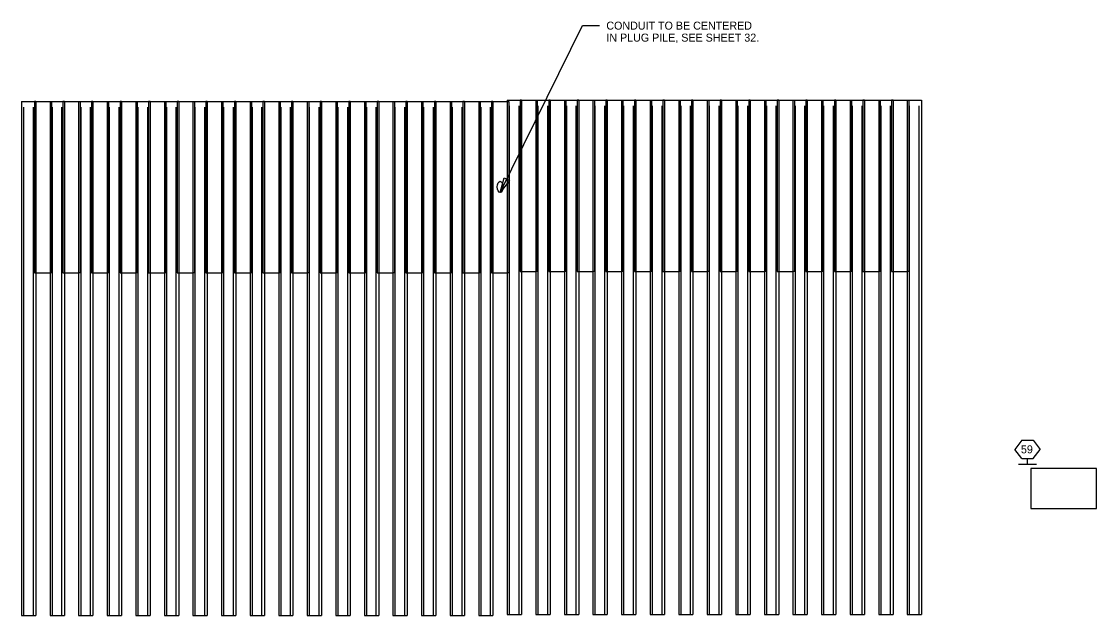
# Model space of a CAD drawing. Extents: x -190 to 421, y 1 to 366.
# Drawn here: x -189.8 to -1.7, y 261.9 to 365.9 of the extents above; entities that cross this region are included whole.
import ezdxf

# ---------------------------------------------------------------- set-up
doc = ezdxf.new("R2010")
doc.units = 0
for name, color, linetype in [('BR_P_Beam_Reinforcing', 7, 'Continuous'), ('DR_P_Culvert', 7, 'Continuous'), ('RD_P_Wall', 7, 'Continuous'), ('SH_Data', 7, 'Continuous')]:
    doc.layers.add(name, color=color, linetype=linetype)

msp = doc.modelspace()

# ---------------------------------------------------------------- linework, layer by layer
at = {"layer": 'BR_P_Beam_Reinforcing'}
for p, q in [((-189.38, 261.93), (-189.38, 350.93)), ((-187.71, 261.93), (-187.71, 350.93)), ((-184.38, 261.93), (-184.38, 350.93)), ((-182.71, 261.93), (-182.71, 350.93)), ((-179.38, 261.93), (-179.38, 350.93)), ((-177.71, 261.93), (-177.71, 350.93)), ((-174.38, 261.93), (-174.38, 350.93)), ((-172.71, 261.93), (-172.71, 350.93)), ((-169.38, 261.93), (-169.38, 350.93)), ((-167.71, 261.93), (-167.71, 350.93)), ((-164.38, 261.93), (-164.38, 350.93)), ((-162.71, 261.93), (-162.71, 350.93)), ((-159.38, 261.93), (-159.38, 350.93)), ((-157.71, 261.93), (-157.71, 350.93)), ((-154.38, 261.93), (-154.38, 350.93)), ((-152.71, 261.93), (-152.71, 350.93)), ((-149.38, 261.93), (-149.38, 350.93)), ((-147.71, 261.93), (-147.71, 350.93)), ((-144.38, 261.93), (-144.38, 350.93)), ((-142.71, 261.93), (-142.71, 350.93)), ((-139.38, 261.93), (-139.38, 350.93)), ((-137.71, 261.93), (-137.71, 350.93)), ((-134.38, 261.93), (-134.38, 350.93)), ((-132.71, 261.93), (-132.71, 350.93)), ((-129.38, 261.93), (-129.38, 350.93)), ((-127.71, 261.93), (-127.71, 350.93)), ((-124.38, 261.93), (-124.38, 350.93)), ((-122.71, 261.93), (-122.71, 350.93)), ((-119.38, 261.93), (-119.38, 350.93)), ((-117.71, 261.93), (-117.71, 350.93)), ((-114.38, 261.93), (-114.38, 350.93)), ((-112.71, 261.93), (-112.71, 350.93)), ((-109.38, 261.93), (-109.38, 350.93)), ((-107.71, 261.93), (-107.71, 350.93)), ((-104.38, 262.13), (-104.38, 351.13)), ((-102.71, 262.13), (-102.71, 351.13)), ((-99.38, 262.13), (-99.38, 351.13)), ((-97.71, 262.13), (-97.71, 351.13)), ((-94.38, 262.13), (-94.38, 351.13)), ((-92.71, 262.13), (-92.71, 351.13)), ((-89.38, 262.13), (-89.38, 351.13)), ((-87.71, 262.13), (-87.71, 351.13)), ((-84.38, 262.13), (-84.38, 351.13)), ((-82.71, 262.13), (-82.71, 351.13)), ((-79.38, 262.13), (-79.38, 351.13)), ((-77.71, 262.13), (-77.71, 351.13)), ((-74.38, 262.13), (-74.38, 351.13)), ((-72.71, 262.13), (-72.71, 351.13)), ((-69.38, 262.13), (-69.38, 351.13)), ((-67.71, 262.13), (-67.71, 351.13)), ((-64.38, 262.13), (-64.38, 351.13)), ((-62.71, 262.13), (-62.71, 351.13)), ((-59.38, 262.13), (-59.38, 351.13)), ((-57.71, 262.13), (-57.71, 351.13)), ((-54.38, 262.13), (-54.38, 351.13)), ((-52.71, 262.13), (-52.71, 351.13)), ((-49.38, 262.13), (-49.38, 351.13)), ((-47.71, 262.13), (-47.71, 351.13)), ((-44.38, 262.13), (-44.38, 351.13)), ((-42.71, 262.13), (-42.71, 351.13)), ((-39.38, 262.13), (-39.38, 351.13)), ((-37.71, 262.13), (-37.71, 351.13)), ((-34.38, 262.13), (-34.38, 351.13)), ((-32.71, 262.13), (-32.71, 351.13))]:
    msp.add_line(p, q, dxfattribs=at)
at = {"layer": 'DR_P_Culvert'}
msp.add_ellipse((-106.04, 336.95), major_axis=(0, 1), ratio=0.5, dxfattribs=at)
at = {"layer": 'RD_P_Wall'}
for p, q in [((-189.79, 351.93), (-187.29, 351.93)), ((-189.79, 351.93), (-189.79, 261.93)), ((-187.29, 351.93), (-184.79, 351.93)), ((-187.29, 351.93), (-187.29, 261.93)), ((-184.79, 351.93), (-182.29, 351.93)), ((-184.79, 351.93), (-184.79, 261.93)), ((-182.29, 351.93), (-182.29, 261.93)), ((-182.29, 351.93), (-179.79, 351.93)), ((-179.79, 351.93), (-177.29, 351.93)), ((-179.79, 351.93), (-179.79, 261.93)), ((-177.29, 351.93), (-177.29, 261.93)), ((-177.29, 351.93), (-174.79, 351.93)), ((-174.79, 351.93), (-172.29, 351.93)), ((-174.79, 351.93), (-174.79, 261.93)), ((-172.29, 351.93), (-172.29, 261.93)), ((-172.29, 351.93), (-169.79, 351.93)), ((-169.79, 351.93), (-167.29, 351.93)), ((-169.79, 351.93), (-169.79, 261.93)), ((-167.29, 351.93), (-167.29, 261.93)), ((-167.29, 351.93), (-164.79, 351.93)), ((-164.79, 351.93), (-162.29, 351.93)), ((-164.79, 351.93), (-164.79, 261.93)), ((-162.29, 351.93), (-162.29, 261.93)), ((-162.29, 351.93), (-159.79, 351.93)), ((-159.79, 351.93), (-157.29, 351.93)), ((-159.79, 351.93), (-159.79, 261.93)), ((-157.29, 351.93), (-157.29, 261.93)), ((-157.29, 351.93), (-154.79, 351.93)), ((-154.79, 351.93), (-152.29, 351.93)), ((-154.79, 351.93), (-154.79, 261.93)), ((-152.29, 351.93), (-152.29, 261.93)), ((-152.29, 351.93), (-149.79, 351.93)), ((-149.79, 351.93), (-147.29, 351.93)), ((-149.79, 351.93), (-149.79, 261.93)), ((-147.29, 351.93), (-147.29, 261.93)), ((-147.29, 351.93), (-144.79, 351.93)), ((-144.79, 351.93), (-142.29, 351.93)), ((-144.79, 351.93), (-144.79, 261.93)), ((-142.29, 351.93), (-142.29, 261.93)), ((-142.29, 351.93), (-139.79, 351.93)), ((-139.79, 351.93), (-137.29, 351.93)), ((-139.79, 351.93), (-139.79, 261.93)), ((-137.29, 351.93), (-137.29, 261.93)), ((-137.29, 351.93), (-134.79, 351.93)), ((-134.79, 351.93), (-132.29, 351.93)), ((-134.79, 351.93), (-134.79, 261.93)), ((-132.29, 351.93), (-132.29, 261.93)), ((-132.29, 351.93), (-129.79, 351.93)), ((-129.79, 351.93), (-127.29, 351.93)), ((-129.79, 351.93), (-129.79, 261.93)), ((-127.29, 351.93), (-127.29, 261.93)), ((-127.29, 351.93), (-124.79, 351.93)), ((-124.79, 351.93), (-122.29, 351.93)), ((-124.79, 351.93), (-124.79, 261.93)), ((-122.29, 351.93), (-122.29, 261.93)), ((-122.29, 351.93), (-119.79, 351.93)), ((-119.79, 351.93), (-117.29, 351.93)), ((-119.79, 351.93), (-119.79, 261.93)), ((-117.29, 351.93), (-117.29, 261.93)), ((-117.29, 351.93), (-114.79, 351.93)), ((-114.79, 351.93), (-112.29, 351.93)), ((-114.79, 351.93), (-114.79, 261.93)), ((-112.29, 351.93), (-112.29, 261.93)), ((-112.29, 351.93), (-109.79, 351.93)), ((-109.79, 351.93), (-107.29, 351.93)), ((-109.79, 351.93), (-109.79, 261.93)), ((-107.29, 351.93), (-107.29, 261.93)), ((-107.29, 351.93), (-104.79, 351.93)), ((-104.79, 352.13), (-102.29, 352.13)), ((-104.79, 352.13), (-104.79, 262.13)), ((-102.29, 352.13), (-102.29, 262.13)), ((-102.29, 352.13), (-99.79, 352.13)), ((-100.96, 352.13), (-32.29, 352.13)), ((-99.79, 352.13), (-97.29, 352.13)), ((-99.79, 352.13), (-99.79, 262.13)), ((-97.29, 352.13), (-97.29, 262.13)), ((-97.29, 352.13), (-94.79, 352.13)), ((-94.79, 352.13), (-92.29, 352.13)), ((-94.79, 352.13), (-94.79, 262.13)), ((-92.29, 352.13), (-92.29, 262.13)), ((-92.29, 352.13), (-89.79, 352.13)), ((-89.79, 352.13), (-87.29, 352.13)), ((-89.79, 352.13), (-89.79, 262.13)), ((-87.29, 352.13), (-87.29, 262.13)), ((-87.29, 352.13), (-84.79, 352.13)), ((-84.79, 352.13), (-82.29, 352.13)), ((-84.79, 352.13), (-84.79, 262.13)), ((-82.29, 352.13), (-82.29, 262.13)), ((-82.29, 352.13), (-79.79, 352.13)), ((-79.79, 352.13), (-77.29, 352.13)), ((-79.79, 352.13), (-79.79, 262.13)), ((-77.29, 352.13), (-77.29, 262.13)), ((-77.29, 352.13), (-74.79, 352.13)), ((-74.79, 352.13), (-72.29, 352.13)), ((-74.79, 352.13), (-74.79, 262.13)), ((-72.29, 352.13), (-72.29, 262.13)), ((-72.29, 352.13), (-69.79, 352.13)), ((-69.79, 352.13), (-67.29, 352.13)), ((-69.79, 352.13), (-69.79, 262.13)), ((-67.29, 352.13), (-67.29, 262.13)), ((-67.29, 352.13), (-64.79, 352.13)), ((-64.79, 352.13), (-62.29, 352.13)), ((-64.79, 352.13), (-64.79, 262.13)), ((-62.29, 352.13), (-62.29, 262.13)), ((-62.29, 352.13), (-59.79, 352.13)), ((-59.79, 352.13), (-57.29, 352.13)), ((-59.79, 352.13), (-59.79, 262.13)), ((-57.29, 352.13), (-57.29, 262.13)), ((-57.29, 352.13), (-54.79, 352.13)), ((-54.79, 352.13), (-52.29, 352.13)), ((-54.79, 352.13), (-54.79, 262.13)), ((-52.29, 352.13), (-52.29, 262.13)), ((-52.29, 352.13), (-49.79, 352.13)), ((-49.79, 352.13), (-47.29, 352.13)), ((-49.79, 352.13), (-49.79, 262.13)), ((-47.29, 352.13), (-47.29, 262.13)), ((-47.29, 352.13), (-44.79, 352.13)), ((-44.79, 352.13), (-42.29, 352.13)), ((-44.79, 352.13), (-44.79, 262.13)), ((-42.29, 352.13), (-42.29, 262.13)), ((-42.29, 352.13), (-39.79, 352.13)), ((-39.79, 352.13), (-37.29, 352.13)), ((-39.79, 352.13), (-39.79, 262.13)), ((-37.29, 352.13), (-37.29, 262.13)), ((-37.29, 352.13), (-34.79, 352.13)), ((-34.79, 352.13), (-32.29, 352.13)), ((-34.79, 352.13), (-34.79, 262.13)), ((-32.29, 352.13), (-32.29, 262.13)), ((-187.29, 321.93), (-184.79, 321.93)), ((-182.29, 321.93), (-179.79, 321.93)), ((-177.29, 321.93), (-174.79, 321.93)), ((-172.29, 321.93), (-169.79, 321.93)), ((-167.29, 321.93), (-164.79, 321.93)), ((-162.29, 321.93), (-159.79, 321.93)), ((-157.29, 321.93), (-154.79, 321.93)), ((-152.29, 321.93), (-149.79, 321.93)), ((-147.29, 321.93), (-144.79, 321.93)), ((-142.29, 321.93), (-139.79, 321.93)), ((-137.29, 321.93), (-134.79, 321.93)), ((-132.29, 321.93), (-129.79, 321.93)), ((-127.29, 321.93), (-124.79, 321.93)), ((-122.29, 321.93), (-119.79, 321.93)), ((-117.29, 321.93), (-114.79, 321.93)), ((-112.29, 321.93), (-109.79, 321.93)), ((-107.29, 321.93), (-104.79, 321.93)), ((-102.29, 322.13), (-99.79, 322.13)), ((-97.29, 322.13), (-94.79, 322.13)), ((-92.29, 322.13), (-89.79, 322.13)), ((-87.29, 322.13), (-84.79, 322.13)), ((-82.29, 322.13), (-79.79, 322.13)), ((-77.29, 322.13), (-74.79, 322.13)), ((-72.29, 322.13), (-69.79, 322.13)), ((-67.29, 322.13), (-64.79, 322.13)), ((-62.29, 322.13), (-59.79, 322.13)), ((-57.29, 322.13), (-54.79, 322.13)), ((-52.29, 322.13), (-49.79, 322.13)), ((-47.29, 322.13), (-44.79, 322.13)), ((-42.29, 322.13), (-39.79, 322.13)), ((-37.29, 322.13), (-34.79, 322.13)), ((-15.33, 288.45), (-12.19, 288.45)), ((-189.79, 261.93), (-187.29, 261.93)), ((-184.79, 261.93), (-182.29, 261.93)), ((-179.79, 261.93), (-177.29, 261.93)), ((-174.79, 261.93), (-172.29, 261.93)), ((-169.79, 261.93), (-167.29, 261.93)), ((-164.79, 261.93), (-162.29, 261.93)), ((-159.79, 261.93), (-157.29, 261.93)), ((-154.79, 261.93), (-152.29, 261.93)), ((-149.79, 261.93), (-147.29, 261.93)), ((-144.79, 261.93), (-142.29, 261.93)), ((-139.79, 261.93), (-137.29, 261.93)), ((-134.79, 261.93), (-132.29, 261.93)), ((-129.79, 261.93), (-127.29, 261.93)), ((-124.79, 261.93), (-122.29, 261.93)), ((-119.79, 261.93), (-117.29, 261.93)), ((-114.79, 261.93), (-112.29, 261.93)), ((-109.79, 261.93), (-107.29, 261.93)), ((-104.79, 262.13), (-102.29, 262.13)), ((-99.79, 262.13), (-97.29, 262.13)), ((-94.79, 262.13), (-92.29, 262.13)), ((-89.79, 262.13), (-87.29, 262.13)), ((-84.79, 262.13), (-82.29, 262.13)), ((-79.79, 262.13), (-77.29, 262.13)), ((-74.79, 262.13), (-72.29, 262.13)), ((-69.79, 262.13), (-67.29, 262.13)), ((-64.79, 262.13), (-62.29, 262.13)), ((-59.79, 262.13), (-57.29, 262.13)), ((-54.79, 262.13), (-52.29, 262.13)), ((-49.79, 262.13), (-47.29, 262.13)), ((-44.79, 262.13), (-42.29, 262.13)), ((-39.79, 262.13), (-37.29, 262.13)), ((-34.79, 262.13), (-32.29, 262.13))]:
    msp.add_line(p, q, dxfattribs=at)
for points in [[(-187.29, 351.93), (-187.54, 351.93), (-187.54, 321.93), (-187.29, 321.93)], [(-184.79, 351.93), (-184.54, 351.93), (-184.54, 321.93), (-184.79, 321.93)], [(-182.29, 351.93), (-182.54, 351.93), (-182.54, 321.93), (-182.29, 321.93)], [(-179.79, 351.93), (-179.54, 351.93), (-179.54, 321.93), (-179.79, 321.93)], [(-177.29, 351.93), (-177.54, 351.93), (-177.54, 321.93), (-177.29, 321.93)], [(-174.79, 351.93), (-174.54, 351.93), (-174.54, 321.93), (-174.79, 321.93)], [(-172.29, 351.93), (-172.54, 351.93), (-172.54, 321.93), (-172.29, 321.93)], [(-169.79, 351.93), (-169.54, 351.93), (-169.54, 321.93), (-169.79, 321.93)], [(-167.29, 351.93), (-167.54, 351.93), (-167.54, 321.93), (-167.29, 321.93)], [(-164.79, 351.93), (-164.54, 351.93), (-164.54, 321.93), (-164.79, 321.93)], [(-162.29, 351.93), (-162.54, 351.93), (-162.54, 321.93), (-162.29, 321.93)], [(-159.79, 351.93), (-159.54, 351.93), (-159.54, 321.93), (-159.79, 321.93)], [(-157.29, 351.93), (-157.54, 351.93), (-157.54, 321.93), (-157.29, 321.93)], [(-154.79, 351.93), (-154.54, 351.93), (-154.54, 321.93), (-154.79, 321.93)], [(-152.29, 351.93), (-152.54, 351.93), (-152.54, 321.93), (-152.29, 321.93)], [(-149.79, 351.93), (-149.54, 351.93), (-149.54, 321.93), (-149.79, 321.93)], [(-147.29, 351.93), (-147.54, 351.93), (-147.54, 321.93), (-147.29, 321.93)], [(-144.79, 351.93), (-144.54, 351.93), (-144.54, 321.93), (-144.79, 321.93)], [(-142.29, 351.93), (-142.54, 351.93), (-142.54, 321.93), (-142.29, 321.93)], [(-139.79, 351.93), (-139.54, 351.93), (-139.54, 321.93), (-139.79, 321.93)], [(-137.29, 351.93), (-137.54, 351.93), (-137.54, 321.93), (-137.29, 321.93)], [(-134.79, 351.93), (-134.54, 351.93), (-134.54, 321.93), (-134.79, 321.93)], [(-132.29, 351.93), (-132.54, 351.93), (-132.54, 321.93), (-132.29, 321.93)], [(-129.79, 351.93), (-129.54, 351.93), (-129.54, 321.93), (-129.79, 321.93)], [(-127.29, 351.93), (-127.54, 351.93), (-127.54, 321.93), (-127.29, 321.93)], [(-124.79, 351.93), (-124.54, 351.93), (-124.54, 321.93), (-124.79, 321.93)], [(-122.29, 351.93), (-122.54, 351.93), (-122.54, 321.93), (-122.29, 321.93)], [(-119.79, 351.93), (-119.54, 351.93), (-119.54, 321.93), (-119.79, 321.93)], [(-117.29, 351.93), (-117.54, 351.93), (-117.54, 321.93), (-117.29, 321.93)], [(-114.79, 351.93), (-114.54, 351.93), (-114.54, 321.93), (-114.79, 321.93)], [(-112.29, 351.93), (-112.54, 351.93), (-112.54, 321.93), (-112.29, 321.93)], [(-109.79, 351.93), (-109.54, 351.93), (-109.54, 321.93), (-109.79, 321.93)], [(-107.29, 351.93), (-107.54, 351.93), (-107.54, 321.93), (-107.29, 321.93)], [(-104.79, 351.93), (-104.54, 351.93), (-104.54, 321.93), (-104.79, 321.93)], [(-102.29, 352.13), (-102.54, 352.13), (-102.54, 322.13), (-102.29, 322.13)], [(-99.79, 352.13), (-99.54, 352.13), (-99.54, 322.13), (-99.79, 322.13)], [(-97.29, 352.13), (-97.54, 352.13), (-97.54, 322.13), (-97.29, 322.13)], [(-94.79, 352.13), (-94.54, 352.13), (-94.54, 322.13), (-94.79, 322.13)], [(-92.29, 352.13), (-92.54, 352.13), (-92.54, 322.13), (-92.29, 322.13)], [(-89.79, 352.13), (-89.54, 352.13), (-89.54, 322.13), (-89.79, 322.13)], [(-87.29, 352.13), (-87.54, 352.13), (-87.54, 322.13), (-87.29, 322.13)], [(-84.79, 352.13), (-84.54, 352.13), (-84.54, 322.13), (-84.79, 322.13)], [(-82.29, 352.13), (-82.54, 352.13), (-82.54, 322.13), (-82.29, 322.13)], [(-79.79, 352.13), (-79.54, 352.13), (-79.54, 322.13), (-79.79, 322.13)], [(-77.29, 352.13), (-77.54, 352.13), (-77.54, 322.13), (-77.29, 322.13)], [(-74.79, 352.13), (-74.54, 352.13), (-74.54, 322.13), (-74.79, 322.13)], [(-72.29, 352.13), (-72.54, 352.13), (-72.54, 322.13), (-72.29, 322.13)], [(-69.79, 352.13), (-69.54, 352.13), (-69.54, 322.13), (-69.79, 322.13)], [(-67.29, 352.13), (-67.54, 352.13), (-67.54, 322.13), (-67.29, 322.13)], [(-64.79, 352.13), (-64.54, 352.13), (-64.54, 322.13), (-64.79, 322.13)], [(-62.29, 352.13), (-62.54, 352.13), (-62.54, 322.13), (-62.29, 322.13)], [(-59.79, 352.13), (-59.54, 352.13), (-59.54, 322.13), (-59.79, 322.13)], [(-57.29, 352.13), (-57.54, 352.13), (-57.54, 322.13), (-57.29, 322.13)], [(-54.79, 352.13), (-54.54, 352.13), (-54.54, 322.13), (-54.79, 322.13)], [(-52.29, 352.13), (-52.54, 352.13), (-52.54, 322.13), (-52.29, 322.13)], [(-49.79, 352.13), (-49.54, 352.13), (-49.54, 322.13), (-49.79, 322.13)], [(-47.29, 352.13), (-47.54, 352.13), (-47.54, 322.13), (-47.29, 322.13)], [(-44.79, 352.13), (-44.54, 352.13), (-44.54, 322.13), (-44.79, 322.13)], [(-42.29, 352.13), (-42.54, 352.13), (-42.54, 322.13), (-42.29, 322.13)], [(-39.79, 352.13), (-39.54, 352.13), (-39.54, 322.13), (-39.79, 322.13)], [(-37.29, 352.13), (-37.54, 352.13), (-37.54, 322.13), (-37.29, 322.13)], [(-34.79, 352.13), (-34.54, 352.13), (-34.54, 322.13), (-34.79, 322.13)]]:
    msp.add_lwpolyline(points, dxfattribs=at)
msp.add_lwpolyline([(-13.16, 280.65), (-1.68, 280.65), (-1.68, 287.65), (-13.16, 287.65)], close=True, dxfattribs=at)
at = {"layer": 'SH_Data'}
for p, q in [((-91.63, 365.19), (-88.63, 365.19)), ((-14.76, 292.62), (-15.96, 291.02)), ((-14.76, 292.62), (-12.76, 292.62)), ((-12.76, 292.62), (-11.56, 291.02)), ((-14.76, 289.42), (-15.96, 291.02)), ((-12.76, 289.42), (-11.56, 291.02)), ((-14.76, 289.42), (-12.76, 289.42)), ((-13.76, 288.45), (-13.76, 289.42))]:
    msp.add_line(p, q, dxfattribs=at)
msp.add_lwpolyline([(-106.04, 335.95), (-91.63, 365.19)], dxfattribs=at)
msp.add_lwpolyline([(-106.04, 335.95), (-105.35, 338.54), (-104.41, 338.08)], close=True, dxfattribs=at)

# ---------------------------------------------------------------- texts
for s, p in [('CONDUIT TO BE CENTERED', (-87.45, 364.49)), ('IN PLUG PILE, SEE SHEET 32.', (-87.45, 362.39)), ('59', (-14.9, 290.32))]:
    msp.add_text(s, height=1.4, dxfattribs=at).set_placement(p)

doc.saveas('drawing.dxf')
